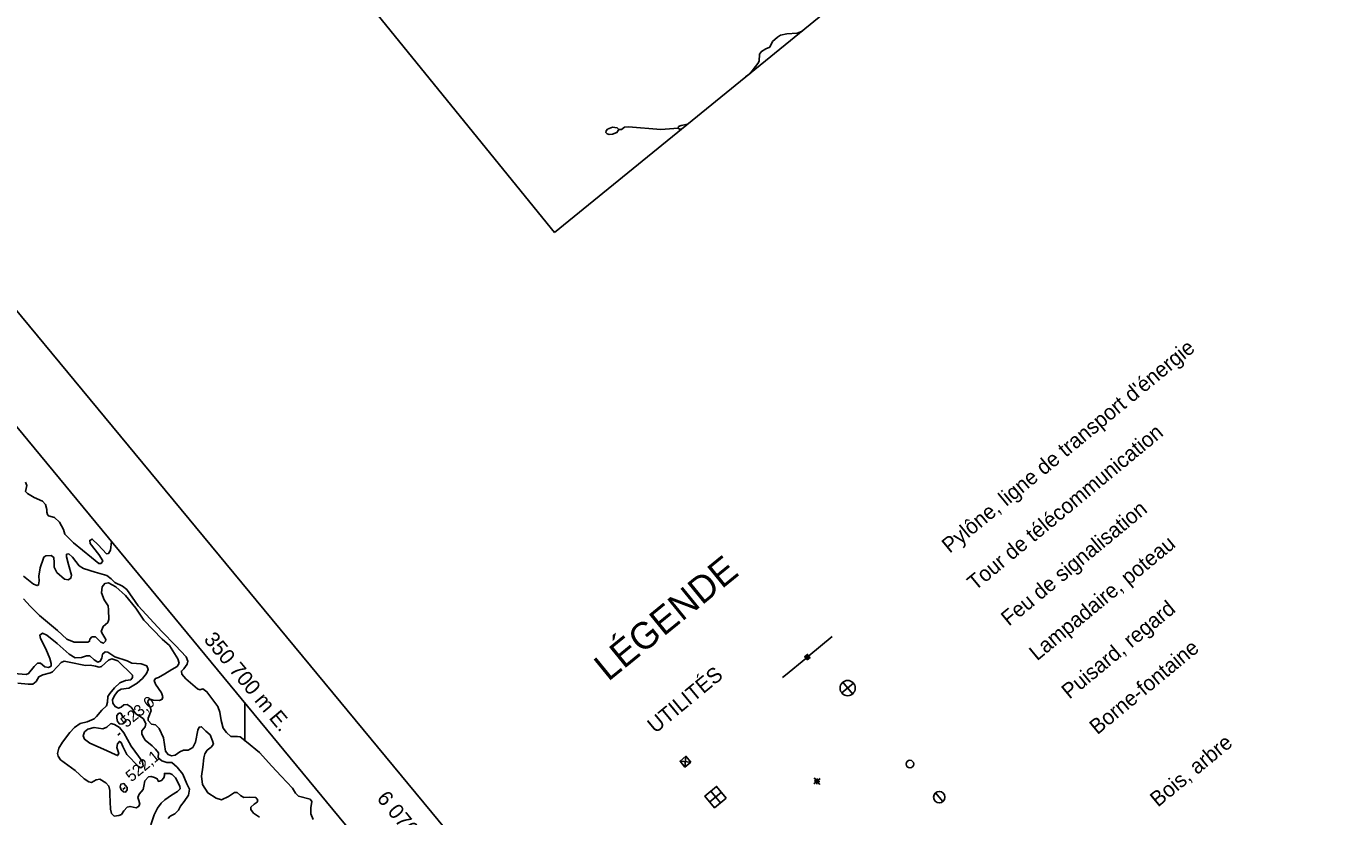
# Model space of a CAD drawing. Extents: x 347059 to 352153, y 6073752 to 6078601.
# Drawn here: x 350614 to 351124, y 6076828 to 6077139 of the extents above; entities that cross this region are included whole.
import ezdxf

# ---------------------------------------------------------------- set-up
doc = ezdxf.new("R2010")
doc.units = 0
for name, color, linetype in [('Level 1', 7, 'Continuous'), ('Level 2', 7, 'Continuous'), ('Level 21', 7, 'Continuous'), ('Level 3', 7, 'Continuous'), ('Level 34', 7, 'Continuous'), ('Level 36', 7, 'Continuous'), ('Level 60', 7, 'Continuous'), ('Level 61', 7, 'Continuous'), ('Level 63', 7, 'Continuous')]:
    doc.layers.add(name, color=color, linetype=linetype)

msp = doc.modelspace()

# ---------------------------------------------------------------- linework, layer by layer
at = {"layer": 'Level 1'}
for points in [[(350660.24, 6076839.59), (350659.98, 6076838.32), (350658.44, 6076836.53), (350657.88, 6076835.15), (350658.27, 6076834.03), (350658.7, 6076832.54), (350658.18, 6076831.59), (350657.27, 6076831.1), (350654.82, 6076831.71), (350653.7, 6076831.32), (350652.35, 6076829.94), (350651.42, 6076828.52), (350650.37, 6076828.05), (350648.56, 6076827.87), (350647.44, 6076828.92), (350647.1, 6076830.61), (350646.86, 6076836.33), (350646.87, 6076837.91), (350646.47, 6076839.68), (350645.3, 6076840.95), (350642.85, 6076842.35), (350641.4, 6076842.21), (350639.64, 6076841.16), (350638.52, 6076841.42), (350636.77, 6076842.6), (350633.2, 6076845.85), (350627.43, 6076850.03), (350626.41, 6076851.43), (350626.22, 6076852.46), (350626.71, 6076854.57), (350628.16, 6076856.94), (350631.05, 6076860.76), (350632.96, 6076862.73), (350635.13, 6076864.38), (350637.85, 6076865.04), (350640.61, 6076866.13), (350641.64, 6076867.11), (350643.67, 6076869.57), (350645.49, 6076871.33), (350645.91, 6076872.73), (350645.99, 6076875.02), (350646.89, 6076876.16), (350648.61, 6076878.36), (350650.74, 6076880.38), (350653.05, 6076881.22), (350655.1, 6076881.59), (350655.82, 6076882.46), (350655.7, 6076883.4), (350649.99, 6076888.95), (350647.63, 6076889.77), (350646.29, 6076889.33), (350643.54, 6076886.8), (350642.58, 6076886.53), (350641.18, 6076886.96), (350639.06, 6076887.32), (350637.19, 6076887.22), (350630.78, 6076888.52), (350628.8, 6076888.86), (350627.6, 6076888.41), (350626.22, 6076886.75), (350624.23, 6076884.72), (350623.4, 6076884.3), (350620.38, 6076883.52), (350618.8, 6076882.75), (350617.83, 6076880.9)], [(350617.83, 6076880.9), (350616.44, 6076879.89), (350614.7, 6076879.77), (350610.58, 6076880.19)], [(350649.65, 6076866.46), (350649.61, 6076867.47), (350650.41, 6076868.39), (350651.14, 6076868.46), (350651.99, 6076866.94), (350653.17, 6076865.81), (350653.11, 6076865.1), (350652.02, 6076864.2), (350650.79, 6076864.11), (350649.81, 6076865.15), (350649.65, 6076866.46)], [(350640.62, 6076862.7), (350644.09, 6076862.27), (350645.65, 6076862.91), (350647.23, 6076864.33), (350648.62, 6076863.9), (350650.59, 6076862.77), (350652.32, 6076860.65), (350655.26, 6076855.46), (350658.11, 6076851.51), (350659.75, 6076849.19), (350659.94, 6076847.51), (350659.02, 6076846.89), (350658.07, 6076847.41), (350653.58, 6076852.11), (350652.02, 6076855.29), (350651.24, 6076856.88), (350650.63, 6076857.3), (350649.83, 6076856.37), (350649.61, 6076854.88), (350650.39, 6076852.5), (350649.88, 6076851.69), (350649.26, 6076851.97), (350645.49, 6076853.72), (350638.95, 6076856.61), (350636.8, 6076858.12), (350636.3, 6076859.54), (350636.8, 6076861), (350638.2, 6076862.15), (350640.62, 6076862.7)], [(350662.95, 6076824.48), (350664.33, 6076828.37), (350665.67, 6076831.05), (350667, 6076832.93), (350668.49, 6076834.29), (350671.18, 6076836.11), (350673.54, 6076837.53), (350674.5, 6076838.58), (350674.39, 6076839.67), (350672.77, 6076842.94), (350671.39, 6076844.3), (350670.42, 6076844.68), (350668.34, 6076844.68), (350668.34, 6076843.89), (350668.1, 6076842.9), (350667.21, 6076841.91), (350665.96, 6076841.53), (350665.55, 6076842.51), (350664.45, 6076843.05), (350663.06, 6076843.48), (350662.04, 6076843.3), (350660.59, 6076841.71), (350660.24, 6076839.59)], [(350651.24, 6076838.25), (350650.92, 6076839.43), (350651.16, 6076840.41), (350652.4, 6076840.65), (350653.68, 6076839.08), (350653.67, 6076838.15), (350653.02, 6076837.35), (350652.16, 6076837.44), (350651.24, 6076838.25)]]:
    msp.add_lwpolyline(points, dxfattribs=at)
at = {"layer": 'Level 2'}
for points in [[(350647.44, 6076936), (350647.44, 6076935.98), (350647.11, 6076932.58), (350646.35, 6076931.3), (350645.55, 6076931.17), (350642.25, 6076934.72), (350639.9, 6076936.96), (350638.92, 6076936.42), (350639.1, 6076935.26), (350642.53, 6076930.9), (350644.01, 6076928.46), (350643.4, 6076927.31), (350642.55, 6076927.39), (350639.63, 6076929.69), (350632.48, 6076935.43), (350629.1, 6076938.92), (350628.64, 6076940.76), (350626.98, 6076943.57), (350625.09, 6076945.41), (350622.66, 6076946.16), (350622.22, 6076946.71), (350622.01, 6076947.58), (350621.97, 6076948.59), (350621.52, 6076950.57), (350620.29, 6076951.91), (350617.07, 6076953.31), (350614.44, 6076954.94), (350613.66, 6076955.73), (350614.18, 6076958.11), (350613.66, 6076959.38)], [(350667.28, 6076900.53), (350657.97, 6076910.65), (350653.51, 6076917.05), (350651.78, 6076918.37), (350648.78, 6076919.82), (350647.34, 6076921.26), (350645.69, 6076922.64), (350641.1, 6076923.97), (350636.52, 6076925.44), (350634.77, 6076926.48), (350632.09, 6076929.9), (350630.71, 6076931.12), (350629.77, 6076931), (350629.82, 6076929.99), (350630.52, 6076926.91), (350631.69, 6076922.78), (350631.43, 6076921.51), (350630.45, 6076920.97), (350628.97, 6076921.19), (350626.01, 6076923.86), (350624.85, 6076925.91), (350624.88, 6076927.77), (350624.71, 6076929.72), (350623.65, 6076930.55), (350621.56, 6076930.4), (350620.8, 6076929.9), (350620.68, 6076929.41), (350619.38, 6076925.6), (350618.79, 6076922.37), (350618.97, 6076920.56), (350618.74, 6076918.93), (350618.21, 6076918.63), (350616.77, 6076919.27), (350612.78, 6076922.4)], [(350673.32, 6076886.83), (350674.16, 6076888.04), (350673.68, 6076889.74), (350670.39, 6076895.02), (350667.49, 6076897.61), (350660.26, 6076905.02), (350657.07, 6076909.72), (350653.05, 6076914.8), (350649.15, 6076918.14), (350646.37, 6076919.78), (350644.83, 6076919.44), (350643.78, 6076918.18), (350643.55, 6076915.76), (350644.58, 6076913.07), (350646.14, 6076910.69), (350646.35, 6076909.16), (350646.48, 6076905.34), (350646.01, 6076904.17), (350644.21, 6076902.56), (350643.45, 6076900.62), (350644.05, 6076899.41), (350645.29, 6076897.42), (350645.08, 6076896.73), (350644.29, 6076895.94), (350643.26, 6076896.41), (350641.24, 6076898.41), (350639.74, 6076898.49), (350638.94, 6076897.56), (350638.85, 6076896.71), (350638.18, 6076896.42), (350632.8, 6076896.32), (350629.84, 6076897.55), (350626.16, 6076900.94), (350619.07, 6076906.9), (350615.48, 6076910.5), (350612.83, 6076913.42)], [(350727, 6076826.56), (350726, 6076828.74), (350726.09, 6076831.17), (350726.4, 6076833.65), (350725.77, 6076834.57), (350721.24, 6076835.67), (350720, 6076836.87), (350718.84, 6076838.92), (350714.36, 6076843.6), (350710.61, 6076847.56), (350705.84, 6076852.92), (350700.68, 6076857.16), (350698.15, 6076859.14), (350697.08, 6076859.18), (350694.45, 6076859.23), (350692.81, 6076860.75), (350691.48, 6076862.54), (350690.76, 6076865.48), (350690.15, 6076868.76), (350689.37, 6076870.99), (350685.08, 6076876.87), (350683.54, 6076877.96), (350682.29, 6076877.58), (350681.4, 6076878.03), (350676.84, 6076881.86), (350675.24, 6076883.81), (350675.07, 6076884.98), (350675.94, 6076885.82), (350677.26, 6076887.7), (350677.51, 6076888.82), (350676.89, 6076890.53), (350672.68, 6076895.04), (350667.28, 6076900.53)], [(350667.38, 6076849.57), (350665.93, 6076850.86), (350665.96, 6076852.73), (350664.82, 6076854.28), (350663.51, 6076855.56), (350660.79, 6076857.78), (350659.79, 6076859.32), (350659.45, 6076860.22), (350659.43, 6076861.51), (350660.71, 6076862.97), (350660.99, 6076864.38), (350659.96, 6076866.28), (350657.13, 6076868.15), (350655.23, 6076870.78), (350653.69, 6076871.87), (350652.38, 6076871.72), (350651.36, 6076870.74), (350650.24, 6076870.35), (350648.94, 6076870.99), (350648.07, 6076872.37), (350647.83, 6076873.62), (350648.64, 6076875.33), (350649.96, 6076877.07), (350651.25, 6076877.87), (350654.3, 6076878.28), (350657.57, 6076880.18), (350659.76, 6076882.12), (350661.23, 6076883.98), (350661.96, 6076885.63), (350661.38, 6076886.99), (350659.16, 6076887.79), (350655.47, 6076888.16), (350653.61, 6076888.99), (350648.82, 6076890.56), (350645.99, 6076892.43), (350644.93, 6076892.61), (350643.98, 6076891.7), (350643.67, 6076890), (350643.06, 6076888.84), (350642.09, 6076888.44), (350640.61, 6076889.45), (350638.89, 6076890.92), (350637.67, 6076890.97), (350635.68, 6076890.38), (350633.23, 6076890.2), (350630.86, 6076891.66), (350626.02, 6076895.82), (350622.04, 6076899.1), (350620.24, 6076899.85), (350619.25, 6076899.16), (350619.55, 6076897.84), (350621.59, 6076893.75), (350623.24, 6076889.98), (350623.76, 6076887.92), (350623.66, 6076886.92), (350622.67, 6076886.37), (350621.19, 6076886.6), (350619.54, 6076888.13), (350618.32, 6076888.04), (350617.04, 6076886.73), (350614.84, 6076884), (350613.87, 6076883.6), (350609.11, 6076884.01)], [(350705.81, 6076827.42), (350703.46, 6076829.02), (350702.39, 6076830.49), (350702.4, 6076831.42), (350703.66, 6076832.59), (350704.95, 6076833.39), (350705.1, 6076834.17), (350704.34, 6076835.25), (350702.06, 6076835.33), (350699.69, 6076835.21), (350698.27, 6076836), (350696.95, 6076837.14), (350695.94, 6076837.1), (350693.65, 6076835.61), (350690.81, 6076834.31), (350688.79, 6076834.88), (350685.49, 6076837), (350683.3, 6076840.31), (350682.97, 6076843.58), (350683.46, 6076847.12), (350683.81, 6076850.81), (350684.25, 6076852.35), (350685.25, 6076853.83), (350686.72, 6076855.04), (350687.62, 6076856.17), (350687.25, 6076857.57), (350686.32, 6076859.82), (350684.6, 6076861.28), (350682.91, 6076863.04), (350682.03, 6076862.84), (350681.56, 6076861.66), (350680.55, 6076857.03), (350679.48, 6076854.84), (350677.67, 6076853.87), (350675.8, 6076853.78), (350674.38, 6076853.13), (350672.6, 6076851.8), (350671.16, 6076851.66), (350669.77, 6076852.09), (350668.76, 6076853.48), (350667.98, 6076858.73), (350666.32, 6076862.34), (350664.88, 6076863.78), (350663.2, 6076864.09), (350661.9, 6076865.52), (350661.92, 6076866.45), (350663.07, 6076869.49), (350662.77, 6076870.81), (350661.8, 6076872.64), (350661.88, 6076873.49), (350662.71, 6076873.91), (350663.89, 6076873.57), (350666.38, 6076873.39), (350667.43, 6076873.86), (350667.66, 6076874.84), (350667.17, 6076876.4), (350664.86, 6076879.86), (350664.35, 6076881.28), (350664.78, 6076882.02), (350665.97, 6076882.48), (350668.46, 6076883.88), (350671.2, 6076885.61), (350673.32, 6076886.83)], [(350669.79, 6076826.89), (350670.67, 6076827.88), (350672.4, 6076828.78), (350673.9, 6076830.14), (350674.63, 6076831.79), (350676.16, 6076833.58), (350677.84, 6076836.14), (350678.2, 6076838.41), (350677.19, 6076840.59), (350675.55, 6076844.35), (350673.31, 6076847.1), (350671.26, 6076848.96), (350669.33, 6076848.94), (350667.38, 6076849.57)]]:
    msp.add_lwpolyline(points, dxfattribs=at)
at = {"layer": 'Level 21'}
for p, q in [((350924.2, 6076840.55), (350926.8, 6076842.66)), ((350926.61, 6076841.49), (350924.39, 6076841.72)), ((350924.43, 6076842.89), (350926.59, 6076840.29)), ((350925.4, 6076840.48), (350925.6, 6076842.7))]:
    msp.add_line(p, q, dxfattribs=at)
at = {"layer": 'Level 3'}
for p, q in [((350650, 6076859.75), (350650.92, 6076860.52)), ((350651.99, 6076838.39), (350652.91, 6076839.16))]:
    msp.add_line(p, q, dxfattribs=at)
at = {"layer": 'Level 34'}
for p, q in [((350939.87, 6076880.17), (350935.28, 6076876.37)), ((350935.67, 6076880.57), (350939.47, 6076875.97)), ((350883.24, 6076833.44), (350887.84, 6076837.27)), ((350883.64, 6076837.66), (350887.44, 6076833.04))]:
    msp.add_line(p, q, dxfattribs=at)
msp.add_lwpolyline([(350889.77, 6076834.94), (350885.14, 6076831.14), (350881.31, 6076835.73), (350885.94, 6076839.56)], close=True, dxfattribs=at)
msp.add_circle((350937.59, 6076878.29), 3, dxfattribs=at)
at = {"layer": 'Level 36'}
for p, q in [((350922.29, 6076890.97), (350931.54, 6076898.6)), ((350913.05, 6076883.34), (350921.14, 6076889.99)), ((350911.9, 6076882.39), (350913.05, 6076883.34)), ((350875.76, 6076849.13), (350871.53, 6076849.53)), ((350873.43, 6076847.2), (350873.83, 6076851.43)), ((350975.11, 6076833.6), (350972.26, 6076837.05))]:
    msp.add_line(p, q, dxfattribs=at)
for points in [[(350921.59, 6076889.42), (350920.64, 6076890.57), (350921.79, 6076891.55), (350922.77, 6076890.37)], [(350875.76, 6076849.13), (350873.43, 6076847.2), (350871.53, 6076849.53), (350873.83, 6076851.43)]]:
    msp.add_lwpolyline(points, close=True, dxfattribs=at)
msp.add_lwpolyline([(350920.91, 6076890.53), (350921.75, 6076891.31), (350921.93, 6076891.1), (350921.09, 6076890.32), (350921.26, 6076890.11), (350922.17, 6076890.82), (350922.35, 6076890.61), (350921.44, 6076889.9), (350921.62, 6076889.66), (350922.5, 6076890.37)], dxfattribs=at)
for centre, radius in [((350962.11, 6076848.37), 1.5), ((350973.69, 6076835.33), 2.25)]:
    msp.add_circle(centre, radius, dxfattribs=at)
at = {"layer": 'Level 60'}
msp.add_line((350700, 6076872.39), (350700, 6076857.39), dxfattribs=at)
for points in [[(349811.7, 6077991.51), (350486.88, 6078550.39), (352105.73, 6076594.68), (351430.55, 6076035.79)], [(347109.95, 6075761.81), (348728.53, 6073803.05), (351407.22, 6076016.53), (349788.63, 6077975.29)]]:
    msp.add_lwpolyline(points, close=True, dxfattribs=at)
at = {"layer": 'Level 63'}
msp.add_lwpolyline([(350822.11, 6077057.72), (351218.14, 6077379.8), (350976.59, 6077676.83), (350580.55, 6077354.75)], close=True, dxfattribs=at)
for points in [[(350899, 6077120.26), (350902.2, 6077124.24), (350902.73, 6077125.22), (350902.8, 6077127.94), (350903.57, 6077129.03), (350905.34, 6077130.08), (350906.87, 6077130.71), (350908, 6077132.88), (350909.91, 6077134.69), (350911.14, 6077135.4), (350913.57, 6077135.92), (350917.7, 6077136.22), (350919.65, 6077137.05)], [(350897.38, 6077118.94), (350897.51, 6077119.14), (350898.51, 6077119.85)], [(350847.39, 6077098.24), (350848.44, 6077098.25), (350849.69, 6077099.14), (350851.21, 6077099.36), (350864, 6077098.31), (350870.78, 6077098.74)], [(350870.78, 6077098.74), (350870.96, 6077099.44), (350871.97, 6077099.91), (350874.52, 6077100.35)], [(350847.39, 6077098.24), (350846.75, 6077098.96), (350844.87, 6077099.19), (350842.96, 6077098.43), (350842.47, 6077097.81), (350842.34, 6077097.14), (350842.86, 6077096.58), (350843.61, 6077096.35), (350844.93, 6077096.41), (350846.66, 6077097.1), (350847.39, 6077098.24)], [(350870.78, 6077098.74), (350871.28, 6077098.4), (350872.12, 6077098.4)]]:
    msp.add_lwpolyline(points, dxfattribs=at)

# ---------------------------------------------------------------- texts
at = {"layer": 'Level 3'}
for s, p in [('523,0', (350653.36, 6076862.46)), ('522,1', (350655.35, 6076841.1))]:
    msp.add_text(s, height=4.5, rotation=39.62, dxfattribs=at).set_placement(p)
at = {"layer": 'Level 60'}
for s, height, rotation, p in [('LÉGENDE', 10.5, 39.1811, (350843.24, 6076880.66)), ('UTILITÉS', 6, 39.5471, (350861.78, 6076860.19))]:
    msp.add_text(s, height=height, rotation=rotation, dxfattribs=at).set_placement(p)
at = {"layer": 'Level 61'}
for s, rotation, p in [('350 700 m E. ', 309.813, (350683.57, 6076897.29)), ('6 076 800 m N.', 309.3644, (350751.72, 6076834.72))]:
    msp.add_text(s, height=6.0001, rotation=rotation, dxfattribs=at).set_placement(p)
at = {"layer": 'Level 63'}
for s, p in [("Pylône, ligne de transport d'énergie", (350977.78, 6076931.16)), ('Tour de télécommunication', (350987.82, 6076916.44)), ('Feu de signalisation', (351001.11, 6076902.46)), ('Lampadaire, poteau', (351012.22, 6076888.78)), ('Puisard, regard', (351024.96, 6076873.7)), ('Borne-fontaine', (351035.97, 6076859.68)), ('Bois, arbre', (351059.84, 6076831.18))]:
    msp.add_text(s, height=5.9999, rotation=39.5471, dxfattribs=at).set_placement(p)

doc.saveas('drawing.dxf')
